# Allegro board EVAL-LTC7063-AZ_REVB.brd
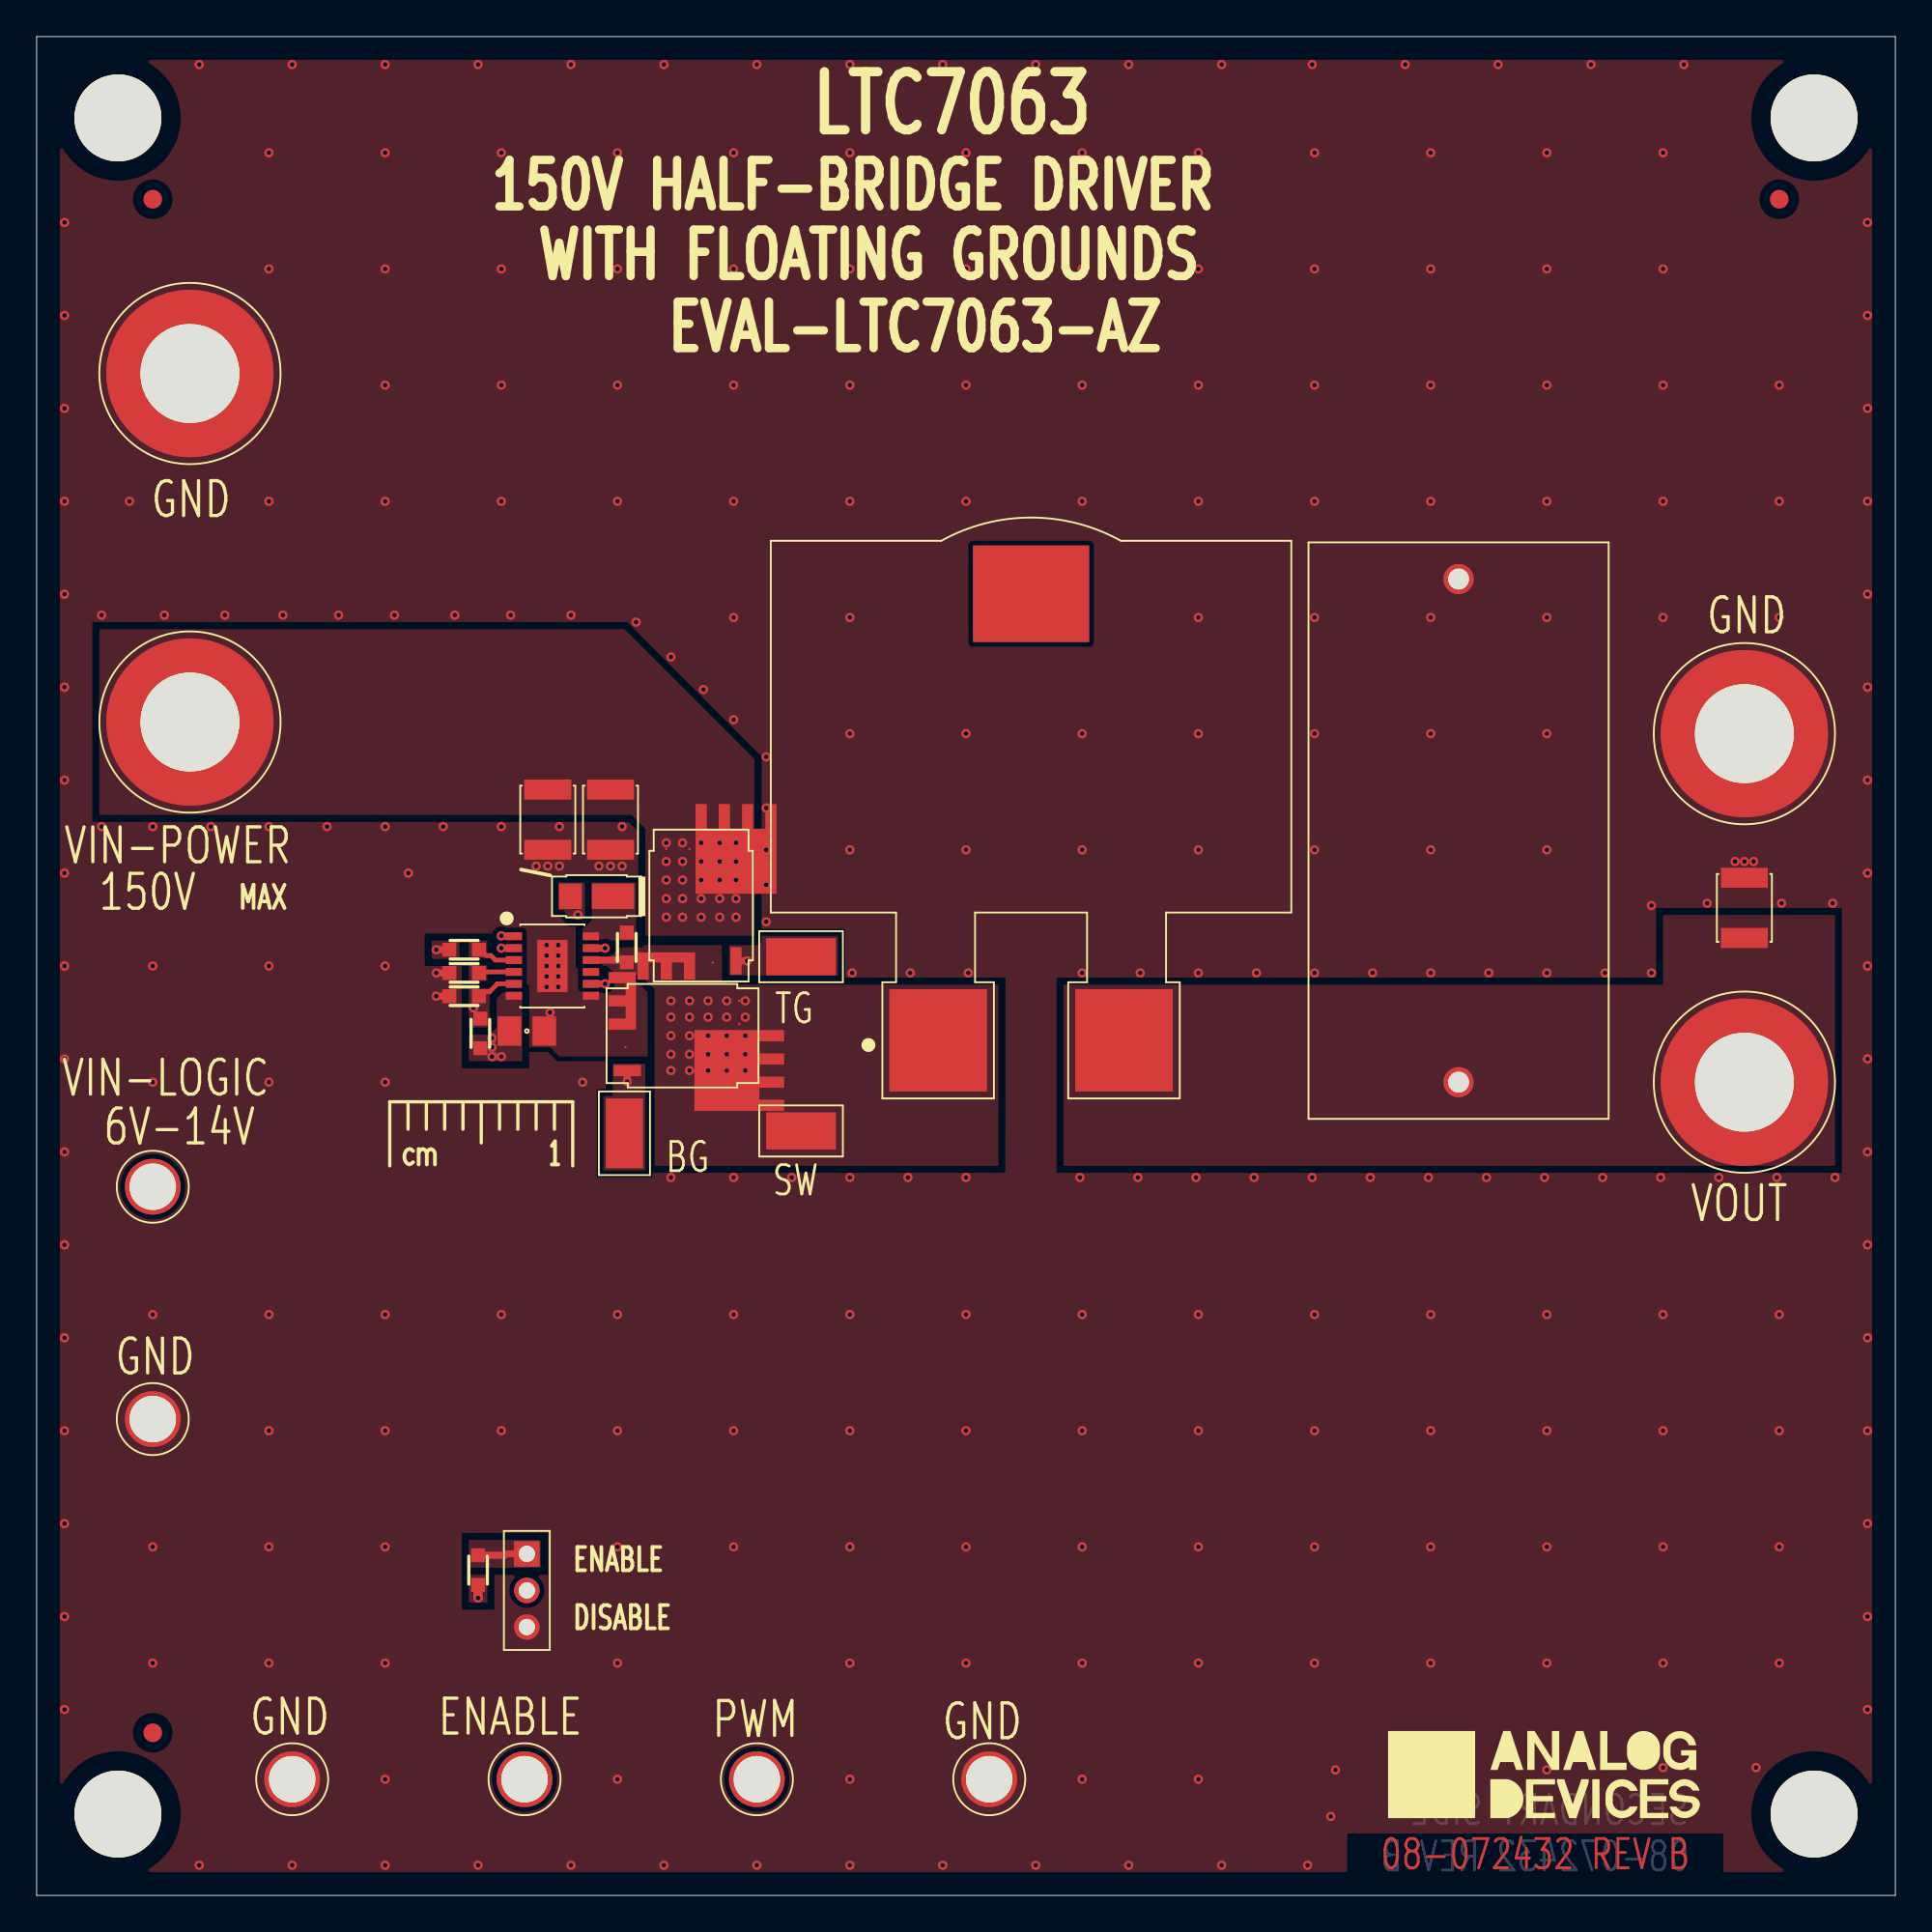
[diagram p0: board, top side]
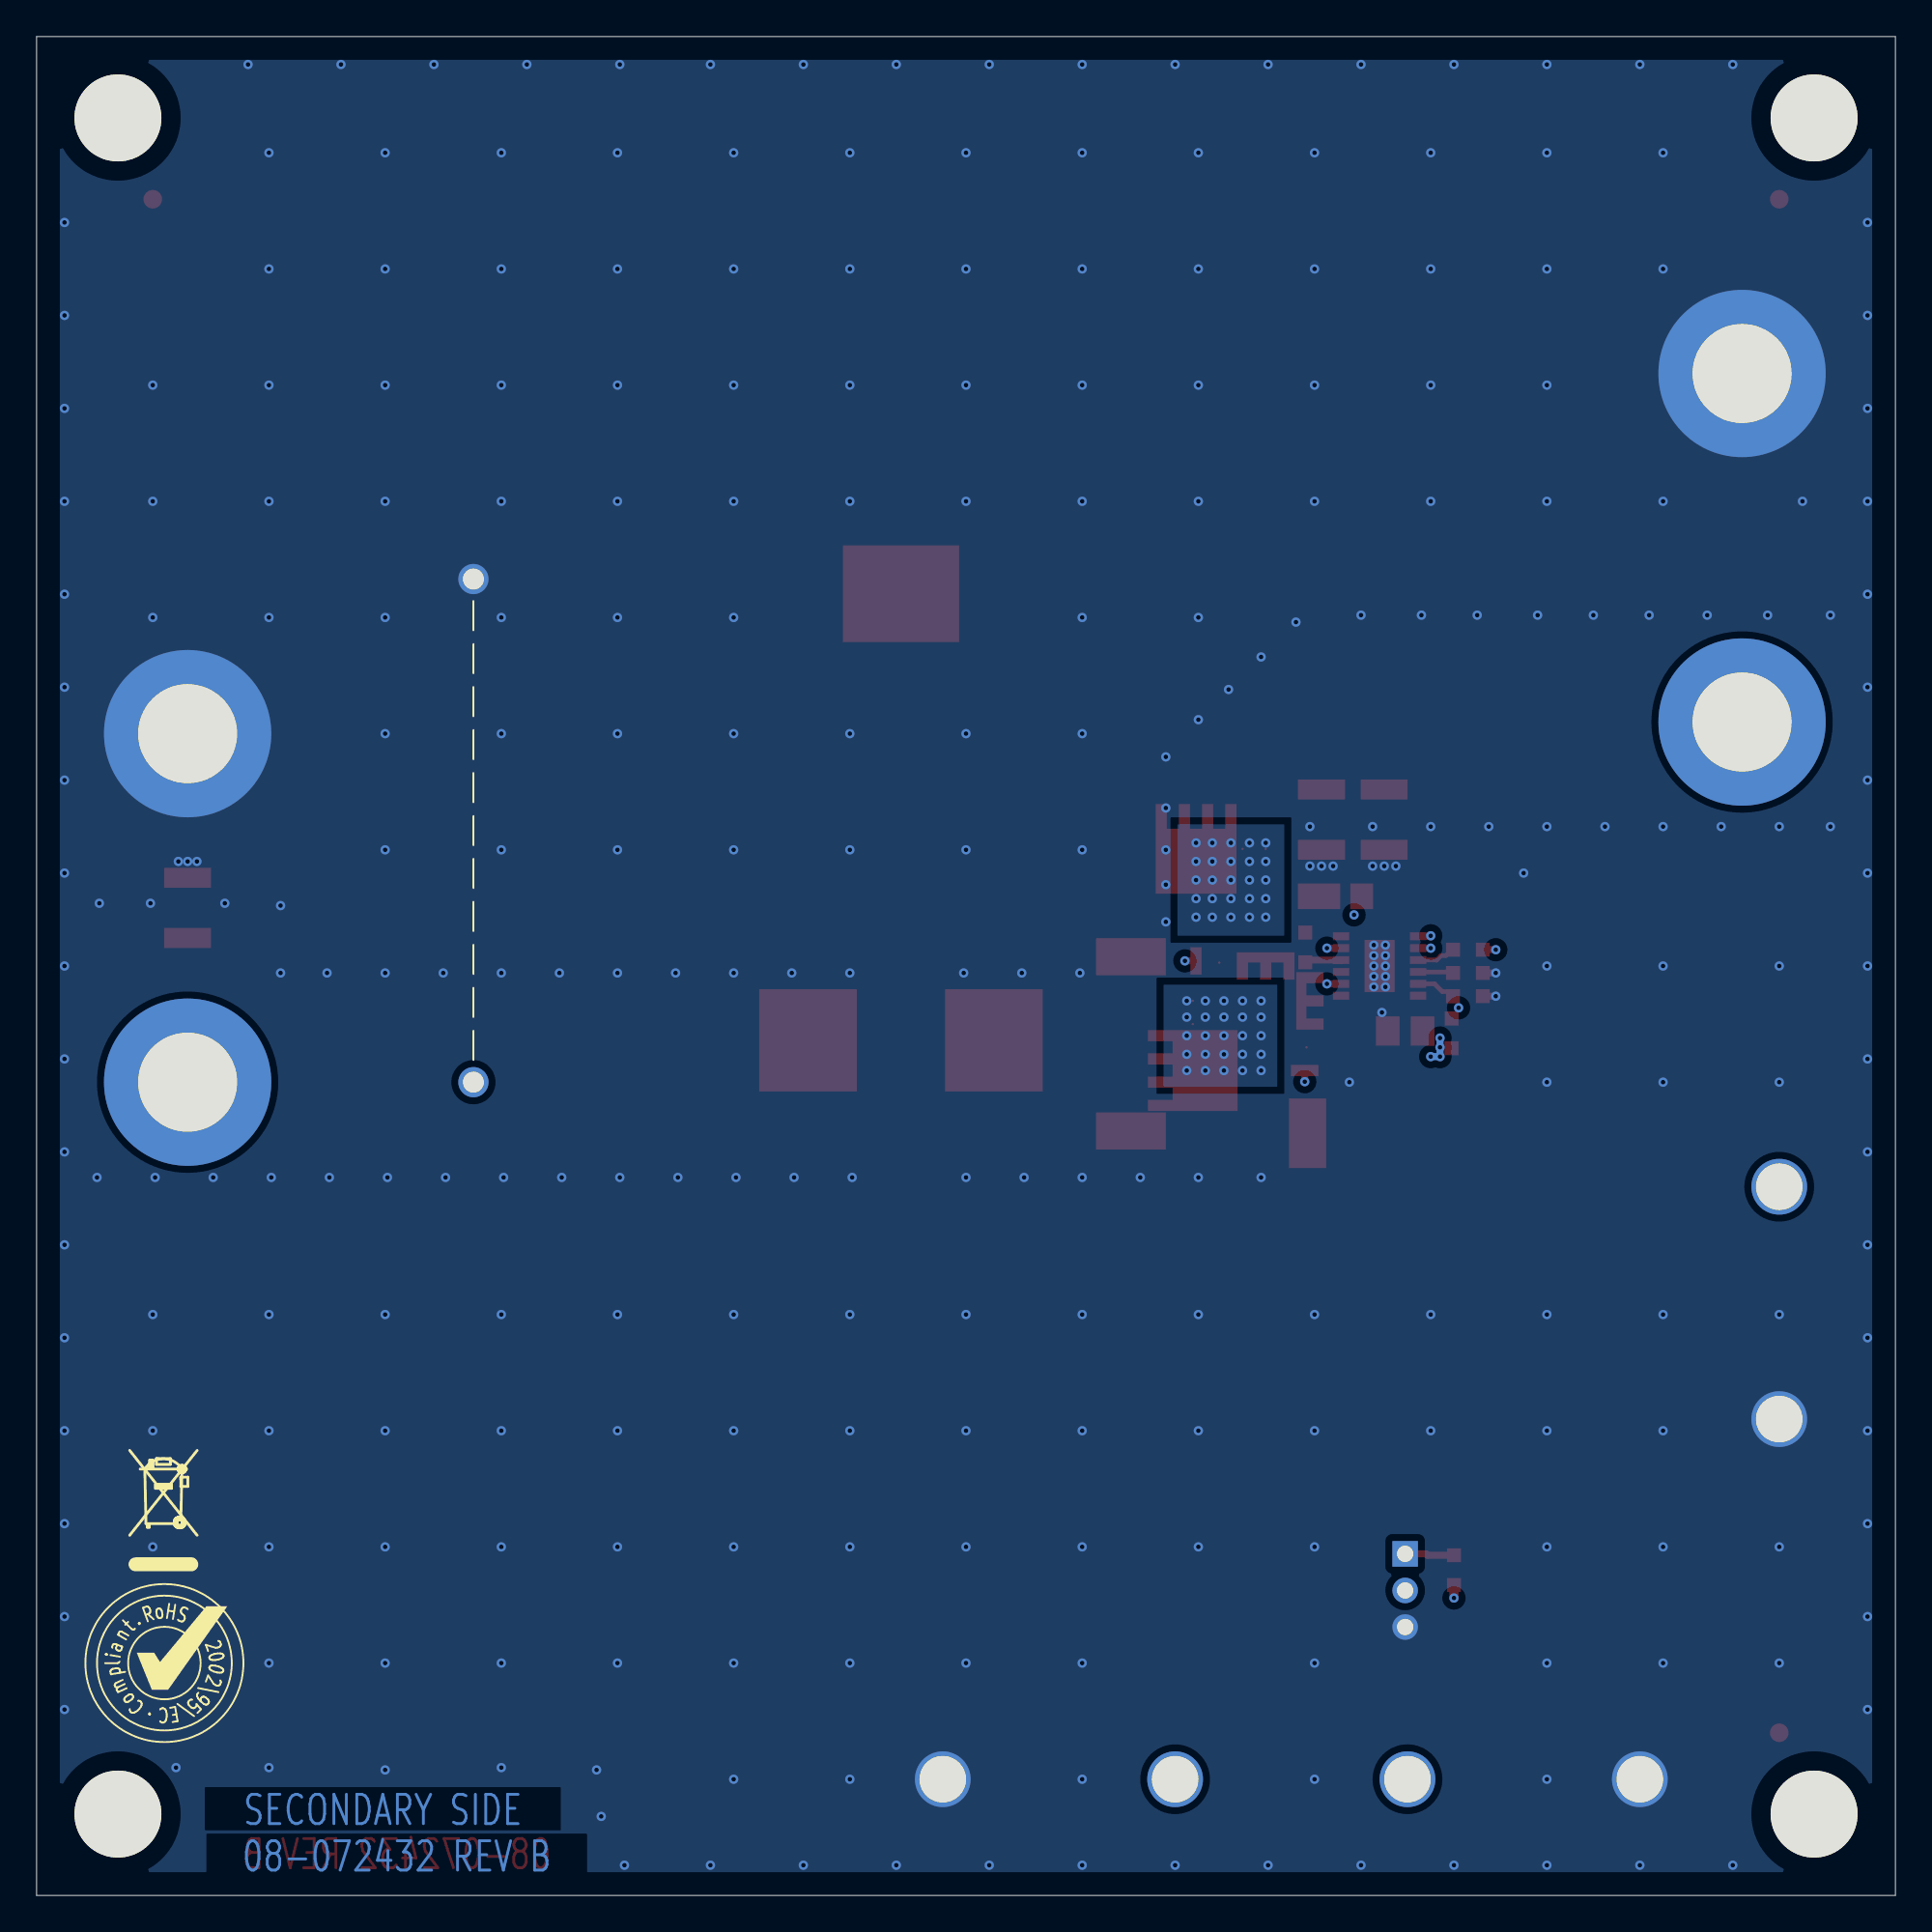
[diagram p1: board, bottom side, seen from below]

Outline 101.6 x 101.6 mm; copper layers: TOP, LAYER_2, LAYER_3, BOTTOM. Coordinates in mm from the lower left corner of the outline.
Outline path: 0,101.6 0,0 101.6,0 101.6,101.6 0,101.6

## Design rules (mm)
constraint set DEFAULT: min track width 0.203

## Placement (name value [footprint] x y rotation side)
C1  1uF  [C0805H60]  26.8 47.24 0 top
C2  1uF  [C0603]  23.37 49.15 0 top
C3  0.22uF  [C0603]  32.26 51.82 270 top
C4  10UF  [CRAD1083L1220W626H1075LD31]  77.72 44.45 90 top
C5  10UF  [C1210H106]  93.34 53.98 90 top
C6  10UF  [C1210H106]  27.94 58.8 270 top
C7  10UF  [C1210H106]  31.37 58.8 270 top
D1  S115FP  [SOD123HE]  30.61 54.61 180 top
JP1  62000311121  [CNTHMHDR1X3L236W79H244]  26.8 18.67 270 top
L1  10UH  [LSML1100W780H605]  54.36 61.09 0 top
NOREF  -  [unnamed]  95.25 92.71 0 top
NOREF#2  -  [#2]  53.98 -5.08 270 top
NOREF#3  -  [#2]  19.3 39.88 0 top
NOREF#4  -  [#2]  256.79 277.75 0 top
NOREF#5  -  [unnamed]  6.35 92.71 0 top
NOREF#6  -  [#2]  -76.2 -76.2 0 top
NOREF#7  -  [unnamed]  97.16 4.45 180 top
NOREF#8  -  [#2]  101.6 0 90 top
NOREF#9  -  [#2]  294.89 163.96 0 top
NOREF#10  -  [#2]  -222.25 -146.05 0 top
NOREF#11  -  [#2]  249.05 252.09 0 top
NOREF#12  -  [#2]  -76.2 -76.2 0 top
NOREF#13  -  [#2]  -222.25 -146.05 0 top
NOREF#14  -  [#2]  -76.2 -76.2 0 top
NOREF#15  -  [#2]  82.42 6.6 0 top
NOREF#16  -  [#2]  20.32 -7.62 0 top
NOREF#17  -  [#2]  63.5 63.5 180 top
NOREF#18  -  [unnamed]  97.16 97.16 180 top
NOREF#19  -  [unnamed]  4.45 97.16 180 top
NOREF#20  -  [#2]  0 0 0 top
NOREF#21  -  [#2]  302.51 96.77 0 top
NOREF#22  -  [unnamed]  6.35 8.89 0 top
NOREF#23  -  [#2]  0 101.6 0 top
NOREF#24  -  [unnamed]  4.45 4.45 180 top
NOREF#25  -  [#2]  63.5 0 90 top
NOREF#26  -  [#2]  289.43 215.01 0 top
NOREF#27  -  [#2]  0 63.5 270 top
NOREF#28  -  [#2]  94.87 17.78 180 bottom
NOREF#29  -  [#2]  94.61 12.7 180 bottom
Q1  BSC074N15NS5ATMA1  [PG-TDSON-8_B]  36.32 54.1 0 top
Q2  BSC074N15NS5ATMA1  [PG-TDSON-8_B]  35.31 46.99 270 top
R1  100K  [R0603]  24.13 17.78 90 top
R2  10  [R0603]  24.26 47.12 90 top
R3  36.5K  [R0603]  23.37 50.42 0 top
R4  51K  [R0603]  23.37 51.69 0 top
TP1  2501-2-00-80-00-00-07-0  [CNMILLMAX2501]  6.35 38.73 0 top
TP2  2501-2-00-80-00-00-07-0  [CNMILLMAX2501]  6.35 26.04 0 top
TP3  2501-2-00-80-00-00-07-0  [CNMILLMAX2501]  26.67 6.35 0 top
TP4  2501-2-00-80-00-00-07-0  [CNMILLMAX2501]  13.97 6.35 0 top
TP5  2501-2-00-80-00-00-07-0  [CNMILLMAX2501]  39.37 6.35 0 top
TP6  2501-2-00-80-00-00-07-0  [CNMILLMAX2501]  52.07 6.35 0 top
TP7  575-4  [CNBANANAD312LD203]  8.38 64.14 0 top
TP8  575-4  [CNBANANAD312LD203]  93.34 44.45 0 top
TP9  575-4  [CNBANANAD312LD203]  8.38 83.19 0 top
TP10  575-4  [CNBANANAD312LD203]  93.34 63.5 0 top
TP11  5019  [CNKEY5019]  41.78 41.78 0 top
TP12  5019  [CNKEY5019]  41.78 51.31 0 top
TP13  5019  [CNKEY5019]  32.13 41.66 90 top
U1  LTC7063RMSE#PBF  [MSOP12_PAD2_845X1_651_05-08-1666]  28.19 50.8 270 top

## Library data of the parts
C1 = CAP: Tolerance: 10; User Part Number: UPN; alternate symbols: (); part number: CAP_SM-1UF,50V,10,E030886,C0805H60; tolerance: 10
C2 = CAP: Tolerance: 10; User Part Number: UPN; alternate symbols: (C0603L); part number: CAP_SM-1UF,25V,10,E034292,C0603; tolerance: 10
C3 = CAP: Tolerance: 10; User Part Number: UPN; alternate symbols: (C0603-27_5AIRGAP); part number: CAP_SM-0.22UF,50V,10,E015565,C0603; tolerance: 10
C4 = CAP: User Part Number: UPN; Tolerance: 10; alternate symbols: (); part number: CAP_TH-10UF,250V,10,E058068,CRAD1083L1220W626H1075LD31; tolerance: 10
C5-C7 = CAP: Tolerance: 10; User Part Number: UPN; alternate symbols: (C1210L); part number: CAP_SM-10UF,100V,10,E044329,C1210H106; tolerance: 10
D1 = DIOSCHOTTKY: User Part Number: UPN; Tolerance: N/A; alternate symbols: (); part number: DIOSCHOTTKY_SM-S115FP,150V,N/A,E046225,SOD123HE; tolerance: N/A
JP1 = CN3P: User Part Number: UPN; Tolerance: N/A; alternate symbols: (); part number: CN3P_TH-62000311121,E033291,CNTHMHDR1X3L236W79H244; tolerance: N/A
L1 = IND: User Part Number: UPN; Tolerance: 10; alternate symbols: (); part number: IND_SM-10UH,10,E045888,LSML1100W780H605; tolerance: 10
Q1 Q2 = TRANNMOSFET8P: Tolerance: N/A; User Part Number: UPN; alternate symbols: (); part number: TRANNMOSFET8P_SM-BSC074N15NS5ATMA1,E058067,PG-TDSON-8_B; tolerance: N/A
R1 = RES: Tolerance: 1; User Part Number: UPN; alternate symbols: (R0603L); part number: RES_SM-100K,E030871,1/10W,1,R0603; tolerance: 1
R2 = RES: Tolerance: 1; User Part Number: UPN; alternate symbols: (R0603L); part number: RES_SM-10,E003666,1/10W,1,R0603; tolerance: 1
R3 = RES: Tolerance: 1; User Part Number: UPN; alternate symbols: (R0603L); part number: RES_SM-36.5K,E011130,1/10W,1,R0603; tolerance: 1
R4 = RES: Tolerance: 1; User Part Number: UPN; alternate symbols: (R0603L); part number: RES_SM-51K,E014698,1/10W,1,R0603; tolerance: 1
TP1-TP6 = CNTP1P: User Part Number: UPN; Tolerance: N/A; alternate symbols: (); part number: CNTP1P_TH-2501-2-00-80-00-00-07-0,E031108,CNMILLMAX2501; tolerance: N/A
TP7-TP10 = CNTP1P: Tolerance: N/A; User Part Number: UPN; alternate symbols: (); part number: CNTP1P_TH-575-4,E012555,CNBANANAD312LD203; tolerance: N/A
TP11-TP13 = CNTP1P: User Part Number: UPN; Tolerance: N/A; alternate symbols: (); part number: CNTP1P_SM-5019,E021431,CNKEY5019; tolerance: N/A
U1 = ADLTC7063: Tolerance: N/A; User Part Number: UPN; alternate symbols: (); part number: ADLTC7063_SM-LTC7063RMSE#PBF,E058066,MSOP12_PAD2_845X1_651_05-08-1666; tolerance: N/A

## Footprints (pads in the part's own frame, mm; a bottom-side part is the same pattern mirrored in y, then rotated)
C0603
  rect 0.762x0.762 smd: 1(-0.813,0) 2(0.813,0)
C0805H60
  rect 1.295x1.6 smd: 1(-0.953,0) 2(0.953,0)
C1210H106
  rect 1.092x2.565 smd: 1(-1.646,0) 2(1.646,0)
CNBANANAD312LD203
  round 9.144 hole 5.41: 1(0,0)
CNKEY5019
  rect 3.81x2.032 smd: 1(0,0)
CNMILLMAX2501
  round 3.048 hole 2.54: 1(0,0)
CNTHMHDR1X3L236W79H244
  rect 1.397x1.397 hole 0.889: 1(0,0)
  round 1.397 hole 0.889: 2(2,0) 3(4,0)
CRAD1083L1220W626H1075LD31
  round 1.651 hole 1.143: 1(0,0) 2(27.5,0)
LSML1100W780H605
  rect 6.35x5.283 smd: (0,10.058)
  rect 5.334x5.588 smd: 1(-5.08,-14.351) 2(5.08,-14.351)
MSOP12_PAD2_845X1_651_05-08-1666
  rect 0.432x0.889 smd: 1(-1.625,-2.107) 2(-0.975,-2.107) 3(-0.325,-2.107) 4(0.325,-2.107) 5(0.975,-2.107) 6(1.625,-2.107) 7(1.625,2.107) 8(0.975,2.107) 9(0.325,2.107) 10(-0.325,2.107) 11(-0.975,2.107) 12(-1.625,2.107)
  rect 2.845x1.651 smd: 13(0,0)
PG-TDSON-8_B
  custom 0.375x0.375 smd: 1(-1.905,-3.3)
  round 0.127 smd: 2(-0.635,-3.12) 3(0.635,-3.12) 6(0.635,3.097) 7(-0.635,3.097) 8(-1.905,3.097)
  rect 0.61x1.499 smd: 4(1.905,-3.021)
  custom 1.105x1.105 smd: 5(1.905,3.097)
R0603
  rect 0.762x0.762 smd: 1(-0.813,0) 2(0.813,0)
SOD123HE
  rect 1.245x1.397 smd: A(1.431,0)
  rect 2.311x1.397 smd: C(-0.897,0)
unnamed
  round 1.016 smd: (0,0)

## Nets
GND_POWER: C1.2(N2) C2.1 C4.2(N2) C5.2(N2) C6.2(N2) C7.2(N2) JP1.3(N3) Q2.1 Q2.2 Q2.3(S3) R3.1 TP2.1(N1) TP4.1(N1) TP6.1(N1) TP9.1(N1) TP10.1(N1) U1.7 U1.13
VIN: C6.1 C7.1 Q1.5 Q1.6 Q1.7 Q1.8 TP7.1(N1)
VIN-LOGIC: C1.1 D1.A(P) R1.1 R2.1 TP1.1(N1) U1.6
BG: Q2.4 TP13.1(N1) U1.8
EN: JP1.2 TP3.1(N1) U1.2
PWM: TP5.1(N1) U1.1
SW: C3.2(N2) L1.1 Q1.1 Q1.2 Q1.3(S3) Q2.5 Q2.6 Q2.7 Q2.8 TP11.1(N1) U1.10
TG: Q1.4 TP12.1(N1) U1.11
UNNAMED_2_ADLTC7063_I56_BST: C3.1 D1.C U1.12
UNNAMED_2_ADLTC7063_I56_DT: R3.2(N2) U1.4
UNNAMED_2_ADLTC7063_I56_FLTN: R4.2(N2) U1.3
UNNAMED_2_ADLTC7063_I56_VCC: C2.2(N2) R2.2(N2) R4.1 U1.5(VCC)
UNNAMED_2_CAP_I5_N1: C4.1 C5.1 L1.2(N2) TP8.1(N1)
UNNAMED_2_CN3P_I1_N1: JP1.1 R1.2(N2)

Pads without a net: U1 9

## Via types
v1: diameter 0.508, hole 0.254, TOP to BOTTOM, 367 vias

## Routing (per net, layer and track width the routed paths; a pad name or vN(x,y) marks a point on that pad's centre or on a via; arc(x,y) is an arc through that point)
GND_POWER: length 1.4
  TOP w0.381: v1(21.84,49.15) C2.1 ; v1(21.84,50.42) R3.1
  vias: v1(1.52,91.44) v1(1.52,86.36) v1(1.52,81.28) v1(1.52,76.2) v1(1.52,71.12) v1(1.52,66.04) v1(1.52,60.96) v1(1.52,55.88) v1(1.52,50.8) v1(1.52,45.72) v1(1.52,40.64) v1(1.52,35.56) v1(1.52,30.48) v1(1.52,25.4) v1(1.52,20.32) v1(1.52,15.24) v1(1.52,10.16) v1(3.56,69.98) v1(3.56,58.42) v1(5.08,76.2) v1(6.35,58.42) v1(6.35,50.8) v1(6.35,44.45) v1(6.35,31.75) v1(6.35,19.05) v1(6.35,12.7) v1(6.99,69.98) v1(8.89,100.08) v1(8.89,1.65) v1(9.53,58.42) v1(10.29,69.98) v1(12.7,95.25) v1(12.7,88.9) v1(12.7,76.2) v1(12.7,58.42) v1(12.7,50.8) v1(12.7,44.45) v1(12.7,31.75) v1(12.7,25.4) v1(12.7,19.05) v1(12.7,12.7) v1(13.46,69.98) v1(13.97,100.08) v1(13.97,1.65) v1(15.88,58.42) v1(16.51,69.98) v1(19.05,100.08) v1(19.05,95.25) v1(19.05,88.9) v1(19.05,82.55) v1(19.05,76.2) v1(19.05,58.42) v1(19.05,50.8) v1(19.05,44.45) v1(19.05,31.75) v1(19.05,25.4) v1(19.05,19.05) v1(19.05,12.7) v1(19.05,6.35) v1(19.05,1.65) v1(19.56,69.98) v1(20.32,55.88) v1(22.23,58.42) v1(22.86,69.98) v1(24.13,100.08) v1(24.13,1.65) v1(25.4,95.25) v1(25.4,88.9) v1(25.4,82.55) v1(25.4,76.2) v1(25.4,58.42) v1(25.4,31.75) v1(25.4,25.4) v1(25.91,69.98) v1(27.3,56.26) v1(27.94,56.26) v1(27.88,51.94) v1(27.88,51.37) v1(27.88,50.8) v1(27.88,50.23) v1(27.88,49.66) v1(28.07,48.26) v1(28.51,51.94) v1(28.51,51.37) v1(28.51,50.8) v1(28.51,50.23) v1(28.51,49.66) v1(28.57,58.42) v1(28.57,56.26) v1(29.21,100.08) v1(29.21,69.98) v1(29.21,1.65) v1(29.84,44.45) v1(30.73,56.26) v1(31.37,56.26) v1(31.75,95.25) v1(31.75,88.9) v1(31.75,82.55) v1(31.75,76.2) v1(31.75,31.75) v1(31.75,25.4) v1(31.75,19.05) v1(31.75,12.7) v1(31.75,6.35) v1(32,58.42) v1(32,56.26) v1(32.77,69.6) v1(34.29,100.08) v1(34.29,1.65) v1(34.67,67.69) v1(34.67,39.24) v1(36.45,65.91) v1(38.1,95.25) v1(38.1,88.9) v1(38.1,82.55) v1(38.1,76.2) v1(38.1,69.85) v1(38.1,64.26) v1(38.1,39.24) v1(38.1,31.75) v1(38.1,25.4) v1(38.1,19.05) v1(39.37,100.08) v1(39.37,1.65) v1(39.88,62.23) v1(39.88,59.44) v1(39.88,57.15) v1(39.88,55.24) v1(39.88,53.21) v1(41.27,39.24) v1(44.45,100.08) v1(44.45,95.25) v1(44.45,88.9) v1(44.45,82.55) v1(44.45,76.2) v1(44.45,69.85) v1(44.45,63.5) v1(44.45,57.15) v1(44.45,39.24) v1(44.45,31.75) v1(44.45,25.4) v1(44.45,19.05) v1(44.45,12.7) v1(44.45,6.35) v1(44.45,1.65) v1(44.58,50.42) v1(47.62,39.24) v1(47.75,50.42) v1(49.53,100.08) v1(49.53,1.65) v1(50.8,95.25) v1(50.8,88.9) v1(50.8,82.55) v1(50.8,76.2) v1(50.8,63.5) v1(50.8,57.15) v1(50.8,39.24) v1(50.8,31.75) v1(50.8,25.4) v1(50.8,19.05) v1(50.8,12.7) v1(50.93,50.42) v1(54.61,100.08) v1(54.61,1.65) v1(57.02,39.24) v1(57.15,95.25) v1(57.15,88.9) v1(57.15,82.55) v1(57.15,76.2) v1(57.15,63.5) v1(57.15,57.15) v1(57.15,50.42) v1(57.15,31.75) v1(57.15,25.4) v1(57.15,19.05) v1(57.15,12.7) v1(57.15,6.35) v1(59.69,100.08) v1(59.69,1.65) v1(60.2,39.24) v1(60.33,50.42) v1(63.37,39.24) v1(63.5,95.25) v1(63.5,88.9) v1(63.5,82.55) v1(63.5,76.2) v1(63.5,69.85) v1(63.5,63.5) v1(63.5,57.15) v1(63.5,50.42) v1(63.5,31.75) v1(63.5,25.4) v1(63.5,19.05) v1(63.5,12.7) v1(63.5,6.35) v1(64.77,100.08) v1(64.77,1.65) v1(66.55,39.24) v1(66.67,50.42) v1(69.47,1.65) v1(69.72,100.08) v1(69.72,39.24) v1(69.85,95.25) v1(69.85,88.9) v1(69.85,82.55) v1(69.85,76.2) v1(69.85,69.85) v1(69.85,63.5) v1(69.85,57.15) v1(69.85,50.42) v1(69.85,31.75) v1(69.85,25.4) v1(69.85,19.05) v1(69.85,12.7) v1(70.74,4.32) v1(70.99,6.86) v1(72.9,39.24) v1(73.03,50.42) v1(74.8,100.08) v1(76.07,39.24) v1(76.2,95.25) v1(76.2,88.9) v1(76.2,82.55) v1(76.2,76.2) v1(76.2,69.85) v1(76.2,63.5) v1(76.2,57.15) v1(76.2,50.42) v1(76.2,31.75) v1(76.2,25.4) v1(76.2,19.05) v1(76.2,12.7) v1(76.2,6.99) v1(79.25,39.24) v1(79.38,50.42) v1(79.88,100.08) v1(82.42,39.24) v1(82.55,95.25) v1(82.55,88.9) v1(82.55,82.55) v1(82.55,76.2) v1(82.55,69.85) v1(82.55,63.5) v1(82.55,57.15) v1(82.55,50.42) v1(82.55,31.75) v1(82.55,25.4) v1(82.55,19.05) v1(82.55,12.7) v1(82.55,6.86) v1(84.96,100.08) v1(85.6,39.24) v1(85.72,50.42) v1(88.27,54.1) v1(88.27,50.42) v1(88.77,39.24) v1(88.9,95.25) v1(88.9,88.9) v1(88.9,82.55) v1(88.9,76.2) v1(88.9,69.85) v1(88.9,31.75) v1(88.9,25.4) v1(88.9,19.05) v1(88.9,12.7) v1(88.9,6.99) v1(90.04,100.08) v1(91.31,54.23) v1(91.95,39.24) v1(92.84,56.52) v1(93.34,56.52) v1(93.85,56.52) v1(93.98,6.99) v1(95.12,39.24) v1(95.25,82.55) v1(95.25,76.2) v1(95.25,69.85) v1(95.25,31.75) v1(95.25,25.4) v1(95.25,19.05) v1(95.25,12.7) v1(95.38,54.23) v1(98.17,54.23) v1(98.3,39.24) v1(100.08,91.44) v1(100.08,86.36) v1(100.08,81.28) v1(100.08,76.2) v1(100.08,71.12) v1(100.08,66.04) v1(100.08,60.96) v1(100.08,55.88) v1(100.08,50.8) v1(100.08,45.72) v1(100.08,40.64) v1(100.08,35.56) v1(100.08,30.48) v1(100.08,25.4) v1(100.08,20.32) v1(100.08,15.24) v1(100.08,10.16)
VIN:
  vias: v1(34.42,57.53) v1(34.42,56.52) v1(34.42,55.5) v1(34.42,54.48) v1(34.42,53.47) v1(35.31,57.53) v1(35.31,56.52) v1(35.31,55.5) v1(35.31,54.48) v1(35.31,53.47) v1(36.32,57.53) v1(36.32,56.52) v1(36.32,55.5) v1(36.32,54.48) v1(36.32,53.47) v1(37.34,57.53) v1(37.34,56.52) v1(37.34,55.5) v1(37.34,54.48) v1(37.34,53.47) v1(38.23,57.53) v1(38.23,56.52) v1(38.23,55.5) v1(38.23,54.48) v1(38.23,53.47)
VIN-LOGIC: length 45.3
  TOP w0.508: R1.1 v1(24.13,16.26)
  LAYER_3 w0.254: v1(24.13,16.26) 24.13,38.73 25.78,40.39 25.78,45.47 v1(25.4,45.85)
  LAYER_3 w0.508: v1(24.89,46.86) 25.02,46.99 25.02,50.16 24,51.18 24,53.09 24.64,53.72 29.46,53.72 v1(29.59,53.59)
  BOTTOM w0.381: v1(25.4,45.85) v1(24.89,45.85) v1(24.89,46.35) v1(24.89,46.86)
BG: length 7.2
  TOP w0.381: Q2.4 v1(32.29,44.48) ; U1.8 v1(31.07,49.82)
  LAYER_3 w0.508: v1(31.07,49.82) 32.29,48.61 v1(32.29,44.48)
EN: length 49.1
  TOP w0.381: U1.2 v1(25.4,51.78)
  LAYER_3 w0.254: TP3.1 26.67,11.81 28.19,13.34 28.19,15.27 JP1.2 28.19,18.07 28.19,38.48 27.18,39.5 27.18,46.74 26.16,47.75 26.16,51.01 v1(25.4,51.78)
PWM: length 53
  TOP w0.381: v1(25.4,52.45) 25.43,52.43 U1.1
  LAYER_3 w0.254: v1(25.4,52.45) 26.04,52.45 27.18,51.31 27.18,48.2 28.57,46.8 28.57,40.26 32.51,36.32 32.51,13.21 TP5.1
SW: length 2
  TOP w0.381: U1.10 32.14,51.13 C3.2
  vias: v1(34.67,48.9) v1(34.67,48.01) v1(34.67,46.99) v1(34.67,45.97) v1(34.67,45.09) v1(35.69,48.9) v1(35.69,48.01) v1(35.69,46.99) v1(35.69,45.97) v1(35.69,45.09) v1(36.7,48.9) v1(36.7,48.01) v1(36.7,46.99) v1(36.7,45.97) v1(36.7,45.09) v1(37.72,48.9) v1(37.72,48.01) v1(37.72,46.99) v1(37.72,45.97) v1(37.72,45.09) v1(38.73,48.9) v1(38.73,48.01) v1(38.73,46.99) v1(38.73,45.97) v1(38.73,45.09)
TG: length 9.4
  TOP w0.381: Q1.4 v1(38.83,51.08) ; U1.11 v1(31.07,51.78)
  LAYER_3 w0.508: v1(31.07,51.78) 38.14,51.78 v1(38.83,51.08)
UNNAMED_2_ADLTC7063_I56_DT: length 1.9
  TOP w0.254: U1.4 24.24,50.47 R3.2
UNNAMED_2_ADLTC7063_I56_FLTN: length 2.1
  TOP w0.254: R4.2 24.24,51.69 24.56,51.37 24.83,51.37 25.07,51.13 U1.3
UNNAMED_2_ADLTC7063_I56_VCC: length 6.9
  TOP w0.254: U1.5 25.19,49.82 24.77,49.4 24.38,49.4 24.18,49.2 C2.2
  TOP w0.381: R4.1 v1(21.84,51.69)
  LAYER_3 w0.254: v1(23.88,48.51) 22.61,49.78 22.61,50.93 v1(21.84,51.69)
UNNAMED_2_CN3P_I1_N1: length 2.7
  TOP w0.381: JP1.1 25.65,18.67 25.58,18.59 R1.2

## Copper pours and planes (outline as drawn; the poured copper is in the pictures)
GND_POWER on TOP: 1.27,100.33 100.33,100.33 100.33,1.27 1.27,1.27 ; 1 cut-out
GND_POWER on BOTTOM: 1.27,100.33 100.33,100.33 100.33,1.27 1.27,1.27
GND_POWER on LAYER_2: 1.27,100.33 100.33,100.33 100.33,1.27 1.27,1.27
GND_POWER on LAYER_3: 1.27,100.33 1.27,1.27 100.33,1.27 100.33,100.33
VIN on TOP: 3.43,69.22 3.43,59.05 32.51,59.05 33.27,58.29 33.27,52.45 39.24,52.45 39.24,62.1 32.13,69.22
VIN on BOTTOM: 33.4,58.55 33.4,52.45 39.24,52.45 39.24,58.55
VIN-LOGIC on TOP: 28.51,55.37 28.51,53.91 28.57,53.85 28.78,53.85 29.27,53.34 29.84,53.34 29.97,53.47 29.97,55.37
VIN-LOGIC on TOP: 23.62,47.05 23.62,45.59 26.54,45.59 26.54,49.4 25.53,49.4 25.15,49.02 25.15,47.43 24.77,47.05
VIN-LOGIC on TOP: 23.62,17.53 23.62,16 24.64,16 24.64,17.53
VIN-LOGIC on LAYER_3: 3.68,41.4 3.68,35.94 19.43,35.94 25.91,42.42 25.91,46.61 25.4,47.12 23.24,47.12 17.53,41.4
BG on TOP: 33.27,45.47 33.27,39.62 30.99,39.62 30.99,43.69 31.5,43.69 31.5,45.47
SW on TOP: 29.84,51.44 29.84,50.93 29.97,50.8 31.18,50.8 31.69,50.29 33.02,50.29 33.78,49.53 33.78,39.88 52.57,39.88 52.58,49.78 37.72,49.78 37.47,50.04 37.47,51.94 32,51.94 31.5,51.44
SW on BOTTOM: 33.78,49.78 33.78,44.2 40.01,44.2 40.01,49.78
TG on TOP: 37.85,51.94 37.85,50.29 43.81,50.29 43.81,52.45 39.5,52.45 39.5,51.94
UNNAMED_2_ADLTC7063_I56_BST on TOP: 29.84,52.2 29.84,52.83 30.35,53.34 30.35,55.37 32.77,55.37 32.77,52.2
UNNAMED_2_ADLTC7063_I56_VCC on TOP: 23.11,52.2 23.11,51.18 21.59,51.18 21.59,52.2
UNNAMED_2_ADLTC7063_I56_VCC on TOP: 23.62,49.66 23.62,47.24 24.89,47.24 24.89,49.66
UNNAMED_2_CAP_I5_N1 on TOP: 98.3,39.88 56.13,39.88 56.13,49.78 88.9,49.78 88.9,53.59 98.3,53.59
UNNAMED_2_CN3P_I1_N1 on TOP: 27.56,19.43 27.56,17.91 23.62,17.91 23.62,19.43

Small or netless copper shapes (teardrops, artwork), in the pictures only: 3 on TOP, 9 on LAYER_3

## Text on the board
BOTTOM: 08-072432 REV B
User.Comments: SOLDER | JP1 - INSTALL SHUNT ACROSS PINS 1-2
TOP: 08-072432 REV B
Ref Des/Silkscreen Top: 150V HALF-BRIDGE DRIVER | WITH FLOATING GROUNDS | EVAL-LTC7063-AZ | LTC7063
PAGE_OUTLINE: 8.   IMPEDANCE REQUIREMENTS: IF NO STACKUP IS DEFINED, THE VENDOR IS ALLOWED TO ADJUST THE DIELECTRIC | 13.  PLATING SPECIFICATION: | 9.   FILLET OPTIONS TO ENHANCE RELIABILITY AT PAD JUNCTIONS WHERE SPACING PERMITS. | 10.  THIEVING: | 11.  LAYER TO LAYER REGISTRATION SHALL BE WITHIN 0.003 INCHES. | 12.  DRILL SIZES ARE FINISHED HOLE SIZES. ALL HOLES SHALL BE LOCATED WITHIN 0.005 INCHES DTP,UNLESS SPECIFIED. | 14.  SURFACE FINISH: | 15.  SOLDERMASK: | 1.   DIMENSIONS ARE IN INCHES (EXCEPT WHERE NOTED). | ALL DOCUMENTS & SPECIFICATIONS REFERRED TO BELOW SHOULD BE THE LATEST REVISIONS. | 2.  BOARD MATERIAL:(USE CHECKED ITEMS) | 3.   ALL LAMINATES & BONDING MATERIALS SHOULD BE SELECTED FROM IPC-4101 OR IPC-4103,(TG>170 DEGC TD>300 DEGC) | 4.   REFER TO IPC-6010 SERIES, CLASS 2 FOR FABRICATION. | 5.   REFER TO LAMINATION DIAGRAM FOR OVERALL BOARD THICKNESS, TOLERANCE APPLIES AFTER ALL LAMINATION AND PLATING | 6.   BOW & TWIST NOT TO EXCEED 0.0075 INCHES (0.75%) PER LINEAR INCH AND SHOULD BE MEASURED PER IPC-TM-650, METHOD 2.4.22. | 7.   ACCEPTABILITY PER ADI SPECIFICATION TST00115. | 16.  APPLY SILKSCREEN TO BOTH SIDES USING A NON-CONDUCTIVE, EPOXY BASED INK PER ARTWORK. | ( ) FILLETS ALLOWED | (X) FILLETS NOT ALLOWED | ( ) VENDOR MAY ADD THIEVING TO COMPENSATE FOR LOW COPPER DENSITY AREAS MAINTAINING A MINIMUM | (X) VENDOR MAY NOT ADD THIEVING TO COMPENSATE FOR LOW COPPER DENSITY AREAS. | (X) LPI | ( ) OTHER_________ | COLOR | ( ) GREEN | (X) OTHER_________ | (X) WHITE | ( ) OTHER | HINDER PROPER SOLDER WICKING. BARREL RELIEF ON SOLDERMASK ALLOWED IN UNFILLED VIA IN PAD HOLES. | (X) REFER TO LAMINATION DIAGRAM FOR FINISHED COPPER WEIGHT/THICKNESS REQUIRMENTS | (X) IMMERSION GOLD (ENIG) 1.58-3.94 MICRO INCHES OVER 118-236 MICRO INCHES MIN. OF ELECTROLESS NICKEL PER IPC-4552 | ( ) OSP (ORGANIC SOLDERABILITY PRESERVATIVE) | ( ) IMMERSION SILVER | ( ) SOFT WIRE BONDABLE GOLD 30-50 MICRO INCHES OF SOFT WIRE | ( ) EDGE CONNECTOR FINGERS ARE TO BE PLATED WITH 100 MICRO-INCHES(.0001") OF LOW STRESS | THICKNESS & TRACE WIDTHS TO MEET THE IMPEDANCE REQUIREMENT. IF SPECIFIED, THE VENDOR MUST | TRACE WIDTH & SPACING THAT IMPACT THE REQUIREMENTS MUST HAVE WRITTEN APPROVAL FROM ADI. | MINIMUM BARREL PLATING OF 0.001 INCHES. PLATED HOLES SHALL NOT BE ROUGH OR IRREGULAR SO AS TO | SOLDERMASK OVER BARE COPPER OR BARE GOLD (BOTH SIDES) TO MEET IPC-SM-840. | IF PRESENT,DO NOT MODIFY SOLDERMASK DEFINED PADS (MASK OPENINGS LESS THAN COPPER PAD) WITHOUT APPROVAL. | MEET THE REQUIREMENTS LISTED IN THE IMPEDANCE TABLE. ANY ADJUSTMENT MADE TO THE DEFINED STACKUP, | PROCESSES. FINISHED THICKNESS MEASURED FROM TOP COPPER TO BOTTOM COPPER. | (X)  ISOLA 370HR OR S1000-2 OR IT180 OR EQUIVALENT | ( )  ISOLA-FR408HR OR EQUIVALENT | ( )  ISOLA IS410 | ( )  MEGTRON 6 | ( )  NELCO-4000-13 | ( )  ROGERS 4350B | ( ) ROGERS 3003 | ( ) ARLON 85N | ( ) EM370D | ( )  OTHER ________________________ | UL FLAMMABILITY RATING 94V-0. BOARD MATERIAL & CONSTRUCTION SHALL MEET THE REQUIREMENTS OF UL796/UL796F. | BONDABLE GOLD OVER 100-150 MICRO INCHES OF NICKEL | NICKEL UNDER 30 MICRO-INCHES (.0003') OF GOLD | 0.100 INCH CLEARANCE FROM ALL COPPER FEATURES, | THE STARTING COPPER WEIGHT/THICKNESS CAN VARY AS LONG AS THE FINISHED COPPER | WEIGHT/THICKNESS IS NOT LESS THAN THE SPECIFIED VALUE. | UNLESS OTHERWISE SPECIFIED | HOMOGENOUS MATERIALS IN THIS BOARD SHALL BE COMPLAINT WITH THE EU DIRECTIVE 2002/95/EC | BLUE | WORKMANSHIP SHALL CONFORM TO IPC-A-600, CLASS 2. | 21.  INTENTIONAL SHORTS: | 17.  FINAL ELECTRICAL TEST TO BE PERFORMED USING PROVIDED IPC-D-356A NETLIST OR ODB++ FORMAT FILE. | 22.  PEMNUTS: | 23.  MANUFACTURER TO ETCH/STAMP WITH PERMANENT NON-CONDUCTIVE INK | ON SECONDARY SIDE UNLESS OTHERWISE SPECIFIED: | 18.  A TIME DOMAIN REFLECTOMETER REPORT (TDR) FOR EACH IMPEDANCE CONTROLLED LAYER & A CERTIFICATE | 19.  IF PRESENT, ALL BLIND/BURIED VIAS WITH AN ASPECT RATIO <1:1 TO BE PLATED SHUT WITH COPPER WHEN | 20.  FOR VIA FILL INFORMATION REFER TO DRILL CHART: | 25. PANELIZATION: | 27.  MINIMUM DESIGN LINE WIDTH IS .005 INCH. | 28.  MINIMUM DESIGN LINE SPACING IS .005 INCH. | FAB NOTES REVISION: 2ND NOVEMBER 2022 | IS ACCEPTABLE, ALL OTHER INSTANCES MUST BE REPORTED. | IF AN INTENTIONAL SHORT REPORT IS SUPPLIED AND DOES NOT MATCH THE FAB DATA THEN | THE PCB SHALL HAVE A VERIFICATION STAMP. | ( )  NON-CONDUCTIVE EPOXY FILL ALL 0.XXXX INCHES DRILLED VIAS | ( )  COPPER FILL ALL 0.XXXX INCHES DRILLED VIAS | ( ) PEMNUTS TO BE INSTALLED BY FABRICATOR | ( ) PEMNUTS NOT TO BE INSTALLED BY FABRICATOR | (X) NOT APPLICABLE | USED AS VIA-IN-PAD OR AS A STACKED VIA. BLIND/BURIED VIAS WITH AN ASPECT RATIO >1:1 TO BE FILLED | A. UL CODE-FLAMMABILITY RATING FOR THOSE APPROVED MATERIALS(IF APPLICABLE) | B. DATE CODE | C. LOT NUMBER | D. MANUFACTURER LOGO | BOARDS TO BE SHIPPED IN ARRAY AND KEPT INTACT | PANEL TO BE SUBJECTED TO CUSTOMERS APPROVAL | PANEL SOLDER PASTE STENCIL GERBER TO BE PROVIDED TO ANALOG | CAN'T BE PERFORMED BECAUSE THE TRACE LENGTH IS TOO SHORT ON THE OUTER LAYERS AT THE PIN ESCAPES | ADI APPROVAL IS REQUIRED. | OF COMPLIANCE SHALL BE PROVIDED BY VENDOR AT TIME OF SHIPMENT. INSTANCES WHERE TDR TESTING | WITH NON-CONDUCTIVE EPOXY. | B | ECR-110751 | 10JAN23 | X | TOOLING: | FINISH: | NOTES: | MATERIAL: | TESTING: | MISCELLANEOUS:
DIMENSION: "0"
User.17: L2 GND | 08-      -07
User.18: 08-      -08 | L3 GND/SIGNAL
User.24: SUPPLY | POWER | CONNECT EN/UVLO | TO GND FOR SHUTDOWN | OPTIONAL | OPTIONAL FOR SYNC | IN | OUT | V | LOAD | I | A | - | +
User.45: FIGURE | SIZE | 10.0 | 35.0 | 45.0 | 100.0 | 213.0 | 187.0 | PLATED | NON-PLATED | FINISHED HOLES IN MILS | ALL UNITS ARE IN MILS | QTY | 367 | 3 | 2 | 6 | 4 | TOLERANCE/NOTES | NO SECONDARY SIDE COMPONENTS
